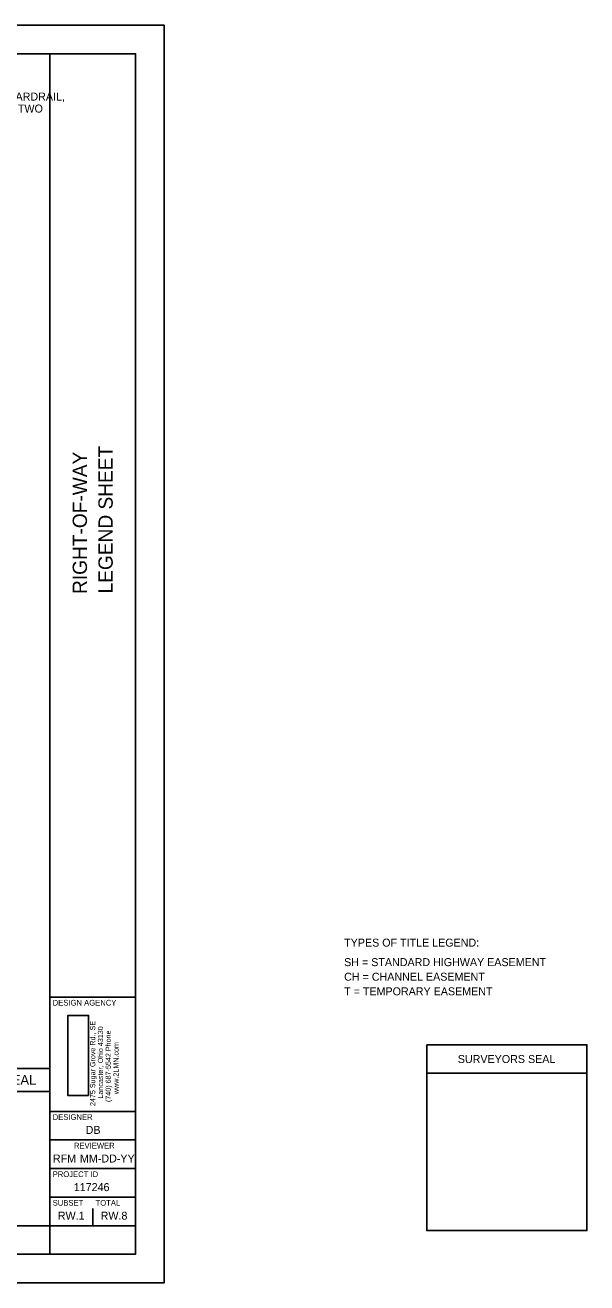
# Model space of a CAD drawing. Extents: x -8.8 to 41.4, y 0 to 34.6.
# Drawn here: x 31.57 to 41.39, y 0 to 22 of the extents above; entities that cross this region are included whole.
import ezdxf

# ---------------------------------------------------------------- set-up
doc = ezdxf.new("R2010")
doc.units = 0
for name, color, linetype in [('SH_Border', 7, 'Continuous'), ('SH_Cut_Line', 7, 'Continuous'), ('SH_Data', 7, 'Continuous'), ('SH_Text', 7, 'Continuous')]:
    doc.layers.add(name, color=color, linetype=linetype)

msp = doc.modelspace()

# ---------------------------------------------------------------- linework, layer by layer
at = {"layer": 'SH_Border'}
for p, q in [((32.75, 4), (32.75, 4)), ((32, 3.75), (29.2, 3.75)), ((32, 0.5), (32, 3.75)), ((38.593, 3.665), (41.393, 3.665)), ((32, 3.35), (29.2, 3.35)), ((32.75, 1), (32.75, 1.3)), ((32, 0.5), (29.2, 0.5))]:
    msp.add_line(p, q, dxfattribs=at)
for points in [[(38.593, 4.165), (41.393, 4.165), (41.393, 0.915), (38.593, 0.915)], [(32, 0.5), (32, 1), (29.2, 1), (29.2, 0.5)]]:
    msp.add_lwpolyline(points, close=True, dxfattribs=at)
at = {"layer": 'SH_Cut_Line'}
for p, q in [((32, 0.5), (32, 21.5)), ((32, 5), (33.5, 5)), ((32, 3), (33.5, 3)), ((32, 2.5), (33.5, 2.5)), ((32, 2), (33.5, 2)), ((32, 1.5), (33.5, 1.5)), ((32, 1), (33.5, 1))]:
    msp.add_line(p, q, dxfattribs=at)
msp.add_lwpolyline([(1.5, 21.5), (33.5, 21.5), (33.5, 0.5), (1.5, 0.5)], close=True, dxfattribs=at)
at = {"layer": 'SH_Data'}
msp.add_lwpolyline([(32.679, 3.276), (32.679, 4.679), (32.316, 4.679), (32.316, 3.276)], close=True, dxfattribs=at)
at = {"layer": 'SH_Text'}
msp.add_lwpolyline([(0, 0), (34, 0), (34, 22), (0, 22)], close=True, dxfattribs=at)

# ---------------------------------------------------------------- texts
at = {"layer": 'SH_Border'}
for s, p in [('RIGHT-OF-WAY', (32.65, 12.05)), ('LEGEND SHEET', (33.1, 12.06))]:
    msp.add_text(s, height=0.25, rotation=90, dxfattribs=at).set_placement(p)
for s, height, p in [('DESIGN AGENCY', 0.1, (32.05, 4.85)), ('SURVEYORS SEAL', 0.14, (39.136, 3.845)), ("SURVEYOR'S SEAL", 0.17, (29.648, 3.465)), ('DESIGNER', 0.1, (32.05, 2.85)), ('DB', 0.14, (32.627, 2.605)), ('REVIEWER', 0.1, (32.422, 2.35)), ('RFM', 0.14, (32.054, 2.105)), ('MM-DD-YY', 0.14, (32.527, 2.105)), ('PROJECT ID', 0.1, (32.05, 1.85)), ('117246', 0.14, (32.419, 1.605)), ('SUBSET', 0.1, (32.05, 1.35)), ('TOTAL', 0.1, (32.8, 1.35)), ('RW.1', 0.14, (32.14, 1.105)), ('RW.8', 0.14, (32.889, 1.105))]:
    msp.add_text(s, height=height, dxfattribs=at).set_placement(p)
at = {"layer": 'SH_Data'}
for s, p in [('THIS PROJECT CONSISTS OF REMOVAL OF EXISTING GUARDRAIL,', (26.189, 20.681)), ('IMPROVEMENT OF ROADSIDE DITCHES AND EXTENDING TWO', (26.189, 20.471)), ('TYPES OF TITLE LEGEND:', (37.148, 5.881)), ('SH = STANDARD HIGHWAY EASEMENT', (37.148, 5.54)), ('CH = CHANNEL EASEMENT', (37.148, 5.285)), ('T = TEMPORARY EASEMENT', (37.148, 5.029))]:
    msp.add_text(s, height=0.14, dxfattribs=at).set_placement(p)
for s, p in [('2475 Sugar Grove Rd., SE  ', (32.795, 3.093)), ('Lancaster, Ohio 43130', (32.931, 3.222)), ('  (740) 687-5542 Phone', (33.067, 3.093)), ('      www.2LMN.com', (33.203, 3.093))]:
    msp.add_text(s, height=0.0906, rotation=90, dxfattribs=at).set_placement(p)

doc.saveas('drawing.dxf')
